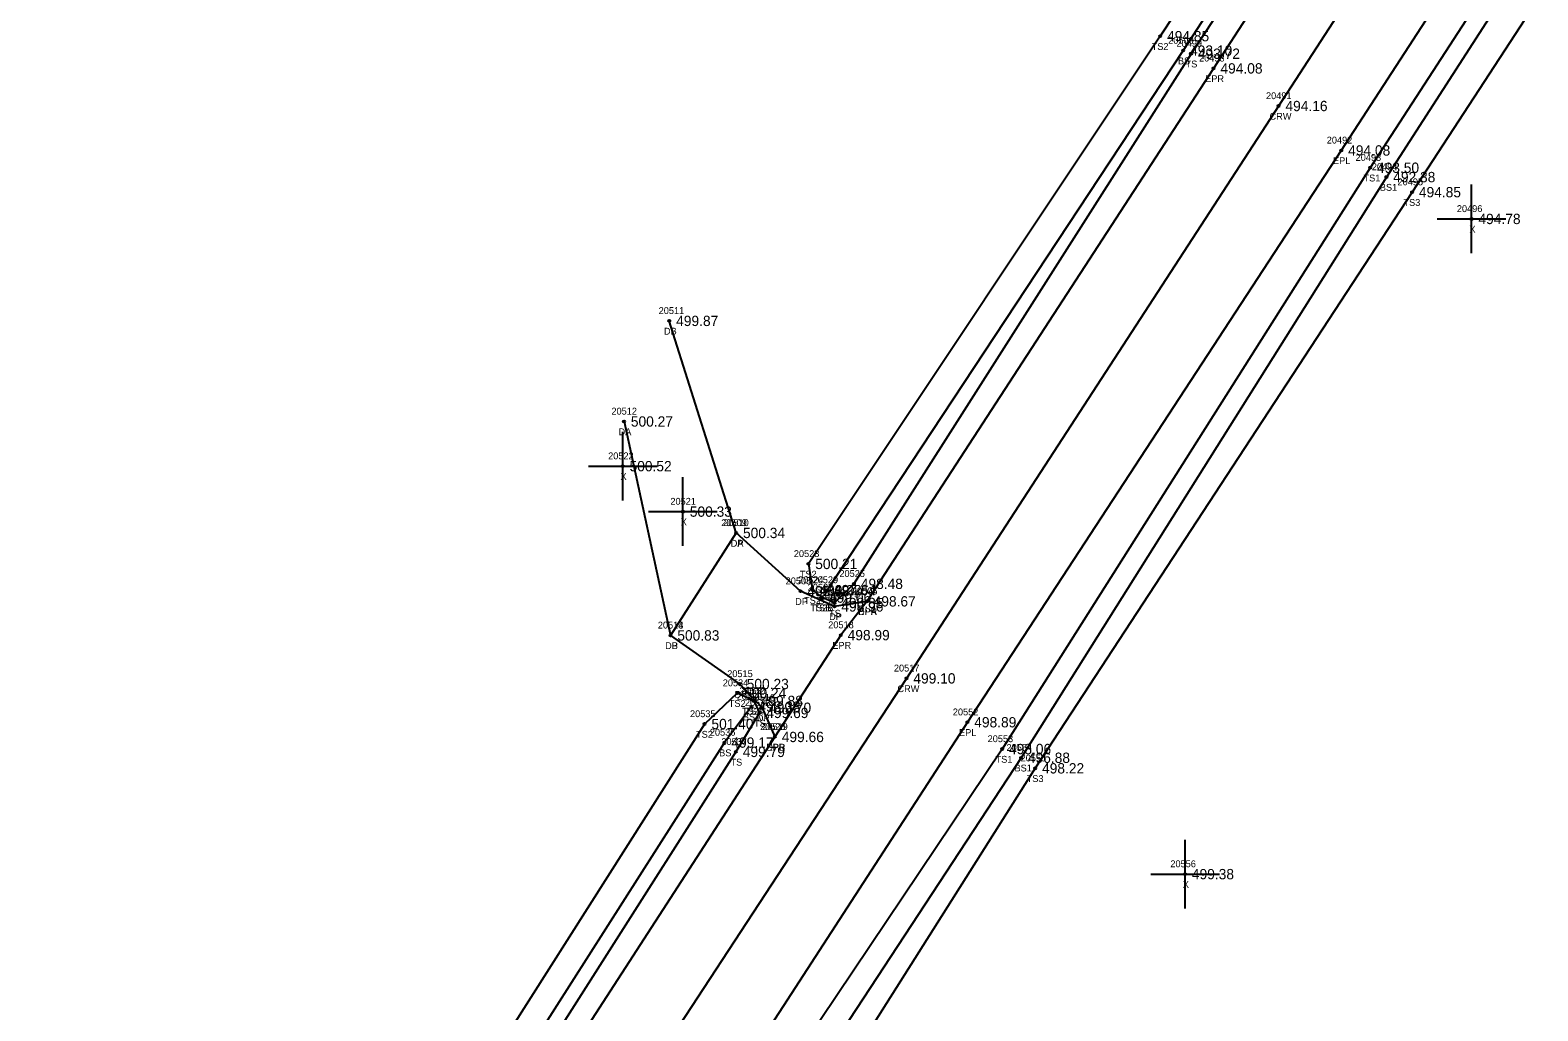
# Model space of a CAD drawing. Extents: x 1741010 to 1742139, y 749382 to 750625.
# Drawn here: x 1741145.5 to 1741365.2, y 749536.3 to 749679.2 of the extents above; entities that cross this region are included whole.
import ezdxf

# ---------------------------------------------------------------- set-up
doc = ezdxf.new("R2010")
doc.units = 0
for name, color, linetype in [('RD_DTM_BkLn1', 7, 'Continuous'), ('RD_DTM_BkLn2', 7, 'Continuous'), ('RD_DTM_BkLn_txCode', 7, 'Continuous'), ('RD_EX_Driveway', 7, 'Continuous'), ('RD_EX_Driveway_txCode', 7, 'Continuous'), ('RD_EX_Misc', 7, 'Continuous'), ('RD_EX_Misc_txCode', 7, 'Continuous'), ('RD_EX_Road', 7, 'Continuous'), ('RD_EX_Road_txCode', 7, 'Continuous'), ('RD_EX_TX_Driveway_ELEV', 7, 'Continuous'), ('RD_EX_TX_Misc_ELEV', 7, 'Continuous'), ('RD_EX_TX_Road_ELEV', 7, 'Continuous'), ('RD_HC_Survey_ELEV', 7, 'Continuous'), ('RD_HC_Survey_txCode', 7, 'Continuous'), ('RD_SMD_Locator', 7, 'Continuous')]:
    doc.layers.add(name, color=color, linetype=linetype)

msp = doc.modelspace()

# ---------------------------------------------------------------- linework, layer by layer
at = {"layer": 'RD_DTM_BkLn1'}
msp.add_lwpolyline([(1741583.42, 750045.09), (1741578.78, 750039.19), (1741548.6, 749999.46), (1741519.68, 749959.35), (1741491.7, 749918.15), (1741464.01, 749876.67), (1741436.51, 749835.23), (1741409.05, 749793.46), (1741381.95, 749752.07), (1741327.4, 749668.12), (1741273.18, 749584.75), (1741218.51, 749501.3), (1741163.8, 749416.96)], dxfattribs=at)
at = {"layer": 'RD_DTM_BkLn2'}
for points in [[(1741595, 750038.14), (1741574.61, 750056.92), (1741567.17, 750063.05), (1741557.5, 750056.24), (1741528.84, 750013.89), (1741502.42, 749971.51), (1741486.02, 749940.89), (1741477.71, 749927.84), (1741450.78, 749885.21), (1741423.85, 749843.58), (1741396.77, 749800.81), (1741369.66, 749759.51), (1741314.64, 749675.74), (1741265.52, 749598.52), (1741262.68, 749595.73), (1741260.89, 749596.52)], [(1741553.69, 750058.21), (1741524.69, 750017.65), (1741497.38, 749974.6), (1741482.49, 749941.95), (1741475.22, 749929.78), (1741449.41, 749886.55), (1741422.56, 749844.68), (1741395.22, 749801.69), (1741368.2, 749760.22), (1741313.51, 749676.19), (1741261.6, 749597.61)], [(1741595, 750038.14), (1741592, 750028.61), (1741562.19, 749990.08), (1741531.32, 749949.92), (1741504.18, 749910.32), (1741476.42, 749868.74), (1741449.21, 749826.98), (1741421.85, 749784.9), (1741395.46, 749743.34), (1741340.74, 749659.13), (1741287.12, 749574.46), (1741231.7, 749491.89), (1741176.84, 749408.86)], [(1741599.45, 750031.16), (1741593.66, 750027.37), (1741564.55, 749987.86), (1741532.82, 749948.93), (1741506.71, 749908.62), (1741479.05, 749867.73), (1741451.41, 749825.96), (1741424.08, 749783.57), (1741397.6, 749742.18), (1741343.11, 749657.77), (1741289.87, 749573.19), (1741234.86, 749489.33), (1741179.61, 749406.64)], [(1741602.3, 750028.04), (1741596.22, 750024.37), (1741565.72, 749986.92), (1741536.13, 749947.45), (1741509.05, 749906.34), (1741480.78, 749866.4), (1741453.63, 749824.8), (1741427.39, 749781.55), (1741401.53, 749739.33), (1741346.85, 749655.57), (1741291.93, 749571.65), (1741238.4, 749487.04), (1741181.74, 749404.39)], [(1741479.58, 749943.23), (1741473.48, 749931.03), (1741447.1, 749888.04), (1741420.34, 749846.09), (1741393.11, 749803.2), (1741365.38, 749761.79), (1741310.15, 749678.29), (1741258.88, 749601.42), (1741259.49, 749597.6), (1741260.89, 749596.52)], [(1741250.94, 749581.46), (1741248.52, 749582.6), (1741243.75, 749578.1), (1741201.31, 749511.38), (1741145.47, 749428.35)], [(1741250.59, 749580.63), (1741246.66, 749575.4), (1741204.53, 749509.36), (1741150.66, 749425.5)], [(1741250.94, 749581.46), (1741251.75, 749579.72), (1741248.32, 749574.04), (1741206.65, 749508.58), (1741152.91, 749423.69)]]:
    msp.add_lwpolyline(points, dxfattribs=at)
at = {"layer": 'RD_EX_Driveway'}
for p, q in [((1741248.35, 749605.93), (1741238.61, 749636.82)), ((1741232.01, 749622.17), (1741238.78, 749591.01))]:
    msp.add_line(p, q, dxfattribs=at)
msp.add_lwpolyline([(1741267.39, 749595.97), (1741262.68, 749595.23), (1741257.73, 749597.45), (1741248.35, 749605.93), (1741238.78, 749591.01), (1741248.89, 749583.93), (1741252.15, 749580.47), (1741254, 749576.22)], dxfattribs=at)
at = {"layer": 'RD_EX_Misc'}
for p, q in [((1741355.53, 749646.67), (1741355.53, 749656.67)), ((1741350.53, 749651.67), (1741360.53, 749651.67)), ((1741231.82, 749610.66), (1741231.82, 749620.66)), ((1741226.82, 749615.66), (1741236.82, 749615.66)), ((1741240.6, 749604.04), (1741240.6, 749614.04)), ((1741235.6, 749609.04), (1741245.6, 749609.04)), ((1741313.77, 749551.24), (1741313.77, 749561.24)), ((1741308.77, 749556.24), (1741318.77, 749556.24))]:
    msp.add_line(p, q, dxfattribs=at)
at = {"layer": 'RD_EX_Road'}
for points in [[(1741574.14, 750053.03), (1741573.09, 750050.35), (1741570.35, 750045.84), (1741539.87, 750005.43), (1741510.87, 749966.19), (1741482.97, 749924.75), (1741454.76, 749883.01), (1741427.14, 749841.37), (1741399.6, 749799.14), (1741372.83, 749758.13), (1741317.93, 749673.6), (1741267.39, 749595.97), (1741263.6, 749591.05), (1741254, 749576.22), (1741209.28, 749507.22), (1741154.74, 749422.71)], [(1741592.65, 750037.91), (1741590.39, 750035.78), (1741587.68, 750032.32), (1741557.76, 749993.29), (1741528.74, 749952.66), (1741501.16, 749912.21), (1741473.5, 749870.53), (1741446.05, 749829.26), (1741418.1, 749787.13), (1741391.18, 749745.79), (1741336.54, 749661.65), (1741282.05, 749578.36), (1741227.71, 749494.6), (1741173.28, 749411)]]:
    msp.add_lwpolyline(points, dxfattribs=at)
at = {"layer": 'RD_SMD_Locator'}
for centre in [(1741310.15, 749678.29), (1741313.51, 749676.19), (1741314.64, 749675.74), (1741317.93, 749673.6), (1741327.4, 749668.12), (1741336.54, 749661.65), (1741340.74, 749659.13), (1741343.11, 749657.77), (1741346.85, 749655.57), (1741355.53, 749651.67), (1741238.61, 749636.82), (1741232.01, 749622.17), (1741231.82, 749615.66), (1741240.6, 749609.04), (1741248.35, 749605.93), (1741248.35, 749605.93), (1741258.88, 749601.42), (1741265.52, 749598.52), (1741257.73, 749597.45), (1741259.49, 749597.6), (1741260.89, 749596.52), (1741260.89, 749596.52), (1741261.6, 749597.61), (1741262.68, 749595.73), (1741267.39, 749595.97), (1741267.39, 749595.97), (1741262.68, 749595.23), (1741238.78, 749591.01), (1741238.78, 749591.01), (1741263.6, 749591.05), (1741273.18, 749584.75), (1741248.52, 749582.6), (1741248.89, 749583.93), (1741250.59, 749580.63), (1741250.94, 749581.46), (1741250.94, 749581.46), (1741252.15, 749580.47), (1741243.75, 749578.1), (1741251.75, 749579.72), (1741282.05, 749578.36), (1741254, 749576.22), (1741254, 749576.22), (1741246.66, 749575.4), (1741248.32, 749574.04), (1741287.12, 749574.46), (1741289.87, 749573.19), (1741291.93, 749571.65), (1741313.77, 749556.24)]:
    msp.add_circle(centre, 0.15, dxfattribs=at)

# ---------------------------------------------------------------- texts
at = {"layer": 'RD_DTM_BkLn_txCode'}
for s, p in [('TS2', (1741308.9, 749676.29)), ('20500', (1741311.31, 749677.19)), ('20499', (1741312.52, 749676.74)), ('BS', (1741312.73, 749674.19)), ('TS', (1741313.85, 749673.74)), ('20493', (1741338.63, 749660.13)), ('20494', (1741340.99, 749658.77)), ('TS1', (1741339.78, 749657.13)), ('20495', (1741344.73, 749656.57)), ('BS1', (1741342.16, 749655.77)), ('TS3', (1741345.6, 749653.57)), ('20523', (1741256.76, 749602.42)), ('TS2', (1741257.63, 749599.42)), ('20525', (1741263.4, 749599.52)), ('20524', (1741257.37, 749598.6)), ('20527', (1741258.78, 749597.52)), ('20528', (1741258.78, 749597.52)), ('20529', (1741259.49, 749598.61)), ('TS2', (1741258.25, 749595.6)), ('BSB', (1741260.35, 749595.61)), ('20526', (1741260.54, 749596.73)), ('TS', (1741264.72, 749596.52)), ('TS2B', (1741259.18, 749594.52)), ('TSB', (1741259.63, 749594.52)), ('TS', (1741261.89, 749593.73)), ('20534', (1741246.4, 749583.6)), ('20530', (1741248.44, 749581.63)), ('20532', (1741248.82, 749582.46)), ('20531', (1741249.1, 749582.46)), ('TS2', (1741247.28, 749580.6)), ('TS2A', (1741249.2, 749579.46)), ('TSA', (1741249.65, 749579.46)), ('20533', (1741249.63, 749580.72)), ('20535', (1741241.63, 749579.1)), ('BSA', (1741249.33, 749578.63)), ('TS', (1741250.95, 749577.72)), ('TS2', (1741242.51, 749576.1)), ('20536', (1741244.52, 749576.4)), ('20537', (1741246.2, 749575.04)), ('20553', (1741285, 749575.46)), ('BS', (1741245.88, 749573.4)), ('20554', (1741287.75, 749574.19)), ('TS', (1741247.53, 749572.04)), ('TS1', (1741286.16, 749572.46)), ('BS1', (1741288.92, 749571.19)), ('20555', (1741289.81, 749572.65)), ('TS3', (1741290.69, 749569.65))]:
    msp.add_text(s, height=1, dxfattribs=at).set_placement(p)
at = {"layer": 'RD_EX_Driveway_txCode'}
for s, p in [('20511', (1741237.06, 749637.82)), ('DB', (1741237.83, 749634.82)), ('20512', (1741230.18, 749623.17)), ('DA', (1741231.22, 749620.17)), ('20509', (1741246.19, 749606.93)), ('20510', (1741246.47, 749606.93)), ('DA', (1741247.55, 749603.93)), ('DP', (1741247.57, 749603.93)), ('20508', (1741255.57, 749598.45)), ('20506', (1741265.21, 749596.97)), ('DP', (1741256.95, 749595.45)), ('20507', (1741260.53, 749596.23)), ('DP', (1741261.9, 749593.23)), ('DPA', (1741266.12, 749593.97)), ('20513', (1741236.94, 749592.01)), ('20514', (1741236.94, 749592.01)), ('DB', (1741238, 749589.01)), ('DP', (1741238, 749589.01)), ('20515', (1741247.05, 749584.93)), ('DP', (1741248.11, 749581.93)), ('20516', (1741250.29, 749581.47)), ('DP', (1741251.37, 749578.47)), ('20520', (1741251.84, 749577.22)), ('DPB', (1741252.75, 749574.22))]:
    msp.add_text(s, height=1, dxfattribs=at).set_placement(p)
at = {"layer": 'RD_EX_Misc_txCode'}
for s, p in [('20496', (1741353.38, 749652.67)), ('X', (1741355.21, 749649.67)), ('20522', (1741229.7, 749616.66)), ('X', (1741231.5, 749613.66)), ('20521', (1741238.77, 749610.04)), ('X', (1741240.28, 749607.04)), ('20556', (1741311.63, 749557.24)), ('X', (1741313.45, 749554.24))]:
    msp.add_text(s, height=1, dxfattribs=at).set_placement(p)
at = {"layer": 'RD_EX_Road_txCode'}
for s, p in [('20498', (1741315.81, 749674.6)), ('EPR', (1741316.7, 749671.6)), ('20492', (1741334.42, 749662.65)), ('EPL', (1741335.34, 749659.65)), ('20505', (1741265.23, 749596.97)), ('EPR', (1741266.16, 749593.97)), ('20518', (1741261.77, 749592.05)), ('EPR', (1741262.37, 749589.05)), ('20552', (1741279.93, 749579.36)), ('20519', (1741252.16, 749577.22)), ('EPL', (1741280.84, 749576.36)), ('EPR', (1741252.77, 749574.22))]:
    msp.add_text(s, height=1, dxfattribs=at).set_placement(p)
at = {"layer": 'RD_EX_TX_Driveway_ELEV'}
for s, p in [('499.87', (1741239.61, 749636.07)), ('500.27', (1741233.01, 749621.42)), ('500.34', (1741249.35, 749605.18)), ('500.34', (1741249.35, 749605.18)), ('499.68', (1741258.73, 749596.7)), ('498.96', (1741263.68, 749594.48)), ('498.67', (1741268.39, 749595.22)), ('500.83', (1741239.78, 749590.26)), ('500.83', (1741239.78, 749590.26)), ('500.23', (1741249.89, 749583.18)), ('499.70', (1741253.15, 749579.72)), ('499.66', (1741255, 749575.47))]:
    msp.add_text(s, height=1.5, dxfattribs=at).set_placement(p)
at = {"layer": 'RD_EX_TX_Misc_ELEV'}
for s, p in [('494.85', (1741311.15, 749677.54)), ('493.10', (1741314.51, 749675.44)), ('493.72', (1741315.64, 749674.99)), ('493.50', (1741341.74, 749658.38)), ('492.38', (1741344.11, 749657.02)), ('494.85', (1741347.85, 749654.82)), ('494.78', (1741356.53, 749650.92)), ('500.52', (1741232.82, 749614.91)), ('500.33', (1741241.6, 749608.29)), ('500.21', (1741259.88, 749600.67)), ('499.22', (1741260.49, 749596.85)), ('497.64', (1741262.6, 749596.86)), ('498.48', (1741266.52, 749597.77)), ('499.06', (1741261.89, 749595.77)), ('499.06', (1741261.89, 749595.77)), ('498.85', (1741263.68, 749594.98)), ('500.24', (1741249.52, 749581.85)), ('498.38', (1741251.59, 749579.88)), ('499.88', (1741251.94, 749580.71)), ('499.88', (1741251.94, 749580.71)), ('499.69', (1741252.75, 749578.97)), ('501.40', (1741244.75, 749577.35)), ('499.17', (1741247.66, 749574.65)), ('499.79', (1741249.32, 749573.29)), ('498.06', (1741288.12, 749573.71)), ('496.88', (1741290.87, 749572.44)), ('498.22', (1741292.93, 749570.9)), ('499.38', (1741314.77, 749555.49))]:
    msp.add_text(s, height=1.5, dxfattribs=at).set_placement(p)
at = {"layer": 'RD_EX_TX_Road_ELEV'}
for s, p in [('494.08', (1741318.93, 749672.85)), ('494.08', (1741337.54, 749660.9)), ('498.67', (1741268.39, 749595.22)), ('498.99', (1741264.6, 749590.3)), ('498.89', (1741283.05, 749577.61)), ('499.66', (1741255, 749575.47))]:
    msp.add_text(s, height=1.5, dxfattribs=at).set_placement(p)
at = {"layer": 'RD_HC_Survey_ELEV'}
for s, p in [('494.16', (1741328.4, 749667.37)), ('499.10', (1741274.18, 749584))]:
    msp.add_text(s, height=1.5, dxfattribs=at).set_placement(p)
at = {"layer": 'RD_HC_Survey_txCode'}
for s, p in [('20491', (1741325.57, 749669.12)), ('CRW', (1741326.09, 749666.12)), ('20517', (1741271.34, 749585.75)), ('CRW', (1741271.86, 749582.75))]:
    msp.add_text(s, height=1, dxfattribs=at).set_placement(p)

doc.saveas('drawing.dxf')
